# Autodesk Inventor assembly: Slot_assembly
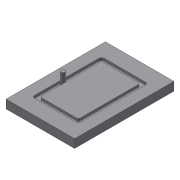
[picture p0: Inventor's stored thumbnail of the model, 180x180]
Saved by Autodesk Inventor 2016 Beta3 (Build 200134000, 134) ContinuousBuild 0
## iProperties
Created: 2016-03
Part Number: Slot_assembly
Document SubType Name: Assembly
Designer: Gaurav
Author: Gaurav
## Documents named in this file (3)
- D:\My Data\Books_Final Books\Autodesk Inventor 2015_resources\Chapter 7\Slot\Slot_assembly.iam
- D:\My Data\Books_Final Books\Autodesk Inventor 2015_resources\Chapter 7\Slot\Base.ipt
- D:\My Data\Books_Final Books\Autodesk Inventor 2015_resources\Chapter 7\Slot\follower.ipt
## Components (2 placed, 2 different names)
1. Base:1 — Mate:1, Mate:4, Mate:5, Transitional:1, Transitional:2
2. follower:1 — Transitional:1, Transitional:2
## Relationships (5: Mate 3, Transitional 2)
- Mate:1: Base:1
- Mate:4: Base:1
- Mate:5: Base:1
- Transitional:1: Base:1 ↔ follower:1
- Transitional:2: Base:1 ↔ follower:1
